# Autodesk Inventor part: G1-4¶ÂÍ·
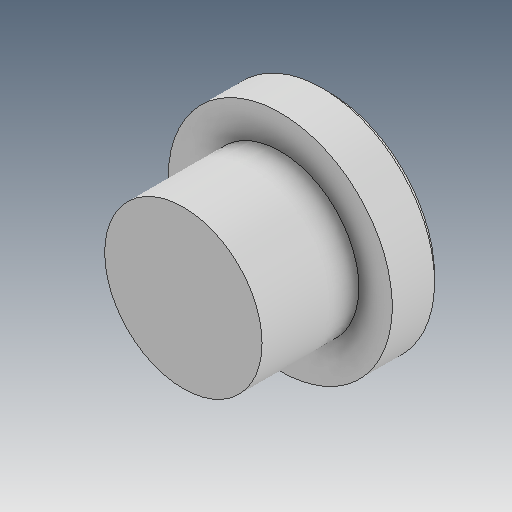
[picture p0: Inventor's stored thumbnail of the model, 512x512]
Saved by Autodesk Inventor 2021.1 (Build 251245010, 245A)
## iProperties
Created: 2019-12
Part Number: G1-4¶ÂÍ·
Material: Ogólny
Document SubType Name: Modeling
Designer: user
Density: 1 g/cm^3
Appearance: Domyślna
Author: user
Revision Number: ÈÎºÎ
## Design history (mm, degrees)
feature "ÊäÈë1"
node "Bryła1"
